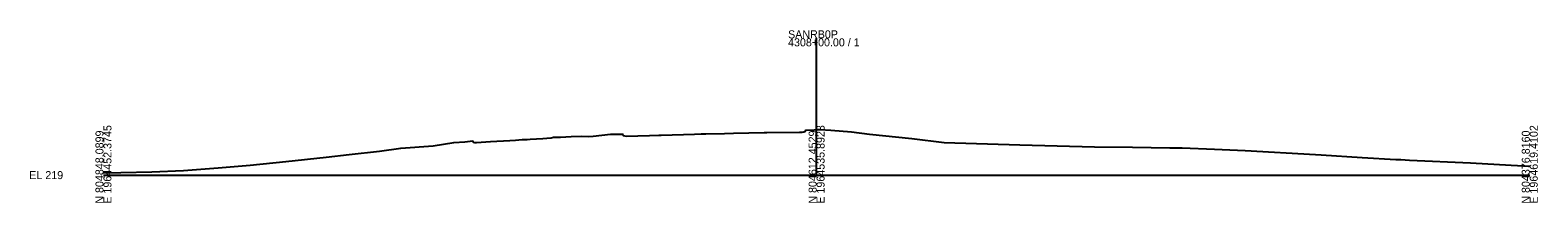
# Model space of a CAD drawing. Extents: x 1995641 to 1997170, y 790368 to 809963.
# Drawn here: x 1996641 to 1997170, y 798868 to 798929 of the extents above; entities that cross this region are included whole.
import ezdxf

# ---------------------------------------------------------------- set-up
doc = ezdxf.new("R2010")
doc.units = 0
for name, color, linetype in [('Default', 7, 'Continuous'), ('RD_GPK_XS_Cell', 7, 'Continuous'), ('RD_Sketch1', 7, 'Continuous'), ('RD_XS_ExGround', 7, 'Continuous')]:
    doc.layers.add(name, color=color, linetype=linetype)

msp = doc.modelspace()

# ---------------------------------------------------------------- linework, layer by layer
at = {"layer": 'RD_GPK_XS_Cell'}
for p, q in [((1996917.06, 798878.11), (1996917.06, 798925.98)), ((1996667.06, 798878.11), (1996917.06, 798878.11)), ((1996917.06, 798878.11), (1997167.06, 798878.11))]:
    msp.add_line(p, q, dxfattribs=at)
at = {"layer": 'RD_XS_ExGround'}
msp.add_lwpolyline([(1996667.06, 798878.92), (1996673.21, 798879.05), (1996684.04, 798879.21), (1996695.12, 798879.74), (1996707.29, 798880.69), (1996718.54, 798881.55), (1996730.98, 798882.85), (1996745.19, 798884.42), (1996753.17, 798885.31), (1996763.8, 798886.49), (1996771.29, 798887.58), (1996782.63, 798888.38), (1996789.86, 798889.49), (1996793.72, 798889.8), (1996796.5, 798890.06), (1996796.63, 798889.61), (1996797.1, 798889.57), (1996797.83, 798889.56), (1996802.74, 798889.85), (1996809.49, 798890.26), (1996811.49, 798890.38), (1996813.84, 798890.54), (1996815.58, 798890.61), (1996816.66, 798890.66), (1996821.12, 798890.95), (1996822.54, 798891.05), (1996823.98, 798891.13), (1996824.84, 798891.36), (1996827.33, 798891.43), (1996831.03, 798891.68), (1996834.57, 798891.7), (1996837.19, 798891.66), (1996838.7, 798891.78), (1996844.81, 798892.49), (1996846.1, 798892.46), (1996849.17, 798892.47), (1996849.27, 798892.02), (1996850.35, 798891.75), (1996858.43, 798892.01), (1996861.7, 798892.11), (1996862.16, 798892.13), (1996862.56, 798892.14), (1996874.27, 798892.45), (1996876.56, 798892.53), (1996878.21, 798892.57), (1996884.82, 798892.69), (1996887.95, 798892.74), (1996898.65, 798893.03), (1996899.6, 798893.05), (1996911.08, 798893.13), (1996912.01, 798893.14), (1996912.62, 798893.29), (1996913.15, 798893.44), (1996913.25, 798893.89), (1996916.21, 798893.99), (1996917.06, 798894.03), (1996918.17, 798894.07), (1996922.07, 798893.89), (1996929.26, 798893.25), (1996935.56, 798892.42), (1996950.48, 798890.94), (1996961.73, 798889.5), (1996988.31, 798888.71), (1997014.51, 798888.05), (1997027.77, 798887.88), (1997040.83, 798887.68), (1997045.24, 798887.64), (1997056.53, 798887.24), (1997064.58, 798886.88), (1997067.29, 798886.74), (1997091.91, 798885.37), (1997093.9, 798885.23), (1997108.32, 798884.25), (1997120.13, 798883.63), (1997121.86, 798883.54), (1997124.89, 798883.37), (1997146.31, 798882.44), (1997160.59, 798881.61), (1997167.06, 798881.27)], dxfattribs=at)

# ---------------------------------------------------------------- texts
at = {"layer": 'Default'}
msp.add_text('-', height=0.0001, dxfattribs=at).set_placement((1996667.06, 798878.11))
msp.add_text('-', height=0.0001, dxfattribs=at).set_placement((1996667.06, 798878.11))
at = {"layer": 'RD_GPK_XS_Cell'}
for s, p in [('4308+00.00 / 1', (1996907.06, 798923.18)), ('SANRB0P', (1996907.06, 798925.98)), ('EL 219', (1996641.06, 798876.71))]:
    msp.add_text(s, height=2.8, dxfattribs=at).set_placement(p)
for s, p in [('N 804848.0899', (1996667.06, 798868.11)), ('E 1964452.3745', (1996669.86, 798868.11)), ('N 804612.4529', (1996917.06, 798868.11)), ('E 1964535.8923', (1996919.86, 798868.11)), ('N 804376.8160', (1997167.06, 798868.11)), ('E 1964619.4102', (1997169.86, 798868.11))]:
    msp.add_text(s, height=2.8, rotation=90, dxfattribs=at).set_placement(p)
at = {"layer": 'RD_Sketch1'}
msp.add_text('234.91', height=0.1, dxfattribs=at).set_placement((1996916.86, 798893.93))

doc.saveas('drawing.dxf')
